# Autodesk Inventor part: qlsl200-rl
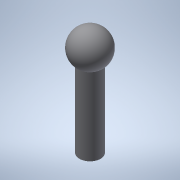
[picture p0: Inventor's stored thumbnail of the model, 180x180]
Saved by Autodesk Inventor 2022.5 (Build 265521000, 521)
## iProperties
Created: 2016-12
Part Number: qlsl200-rl
Material: 一般
Document SubType Name: Modeling
Designer: imaocorp
Density: 1 g/cm^3
Appearance: 既定
Author: imaocorp
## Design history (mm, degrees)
node "qlsl200-rl.x_t1"
node "qlsl200-rl"
node "Base1"
